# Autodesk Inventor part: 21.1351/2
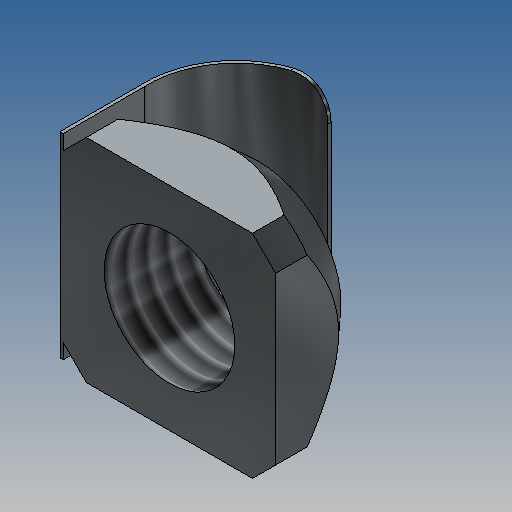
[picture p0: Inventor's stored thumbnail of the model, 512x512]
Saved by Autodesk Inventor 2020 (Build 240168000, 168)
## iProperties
Created: 2006-12
Part Number: 21.1351/2
Document SubType Name: Modeling
Designer: Andy Moles
Material: Steel, Mild
Density: 7.85 g/cm^3
Mass: 4.24899 g
Surface Area: 8.34272 cm^2
Volume: 0.541273 cm^3
Description: M8 SQUARE NUT POS FXG
Vendor: S
Appearance: Zinc
Title: M8 SQUARE NUT POS FXG
Author: Andy Moles
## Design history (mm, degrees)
sketch "Sketch2"
  geometry: L1 (-5.086, -6.5)-(5.086, -6.5); L2 (6.5, -5.086)-(6.5, 5.086); L3 (5.086, 6.5)-(-5.086, 6.5); L4 (-6.5, 5.086)-(-6.5, -5.086); L5 (-6.5, 6.5)-(6.5, -6.5); L6 (5.086, 6.5)-(6.5, 5.086); L7 (0, -6.5)-(0, 6.5); L8 (-6.5, 0)-(6.5, 0); L9 (-5.086, 6.5)-(-6.5, 5.086); L10 (-5.086, -6.5)-(-6.5, -5.086); L11 (5.086, -6.5)-(6.5, -5.086); C1 r 4 at (0, 0); 2 further points
  constraints: 22 end point, 6 symmetric about line, 4 parallel, 3 midpoint, 2 coincident, 2 perpendicular, 1 centre point, 1 horizontal
  dimensions: "THREAD" = 8 diameter of C1; "d3" = 45 deg angle of L3 L6 (derived); "d4" = 2 distance of L3.start L2.end
extrude "Extrusion1" new body sketch "Sketch2" distance "d5" = 5.5; taper "d6" = 0 deg
workplane "Work Plane1"
sketch "Sketch4"
  geometry: L1 (12.192, 0)-(4.192, 0) reference; L2 (8.192, 0)-(13.192, 0); L3 (16.385, 5.5)-(16.385, 3.5); L4 (13.192, 0)-(16.797, 3.952); L5 (13.192, 0)-(16.385, 0); L6 (16.385, 3.5)-(16.385, 0); L7 (16.797, 3.952)-(16.797, -0.412); L8 (16.797, -0.412)-(13.192, -0.412); L9 (13.192, -0.412)-(13.192, 0); L10 (8.192, 5.5)-(8.192, 0); L11 (16.385, 5.5)-(16.385, 0) reference; L12 (16.385, 3.5)-(17.502, 3.5); L13 (9.192, 5.5)-(16.385, 5.5) reference
  constraints: 20 end point, 6 perpendicular, 1 collinear, 1 midpoint, 1 parallel, 1 point on line
  dimensions: "d10" = 5 distance of L2.start L2.end; "d15" = 2 distance between parallel lines of L12 L13
revolve "Revolution1" sketch "Sketch4" stored, may be unused: angle "d12" = 90 deg
thread "Thread1" dims "d13" = 10, "d14" = 0
sketch "Sketch6"
  geometry: L1 (2.954, -2.535)-(2.954, 6.006); L2 (2.954, -2.535)-(2.954, -7.535); L3 (2.954, -2.535)-(3.154, -2.535); L4 (3.154, -2.535)-(3.154, -7.535); L5 (-2.646, -13.135)-(-2.646, -13.335); L6 (2.954, 0)-(2.954, -1.933); L7 (-8.632, -2.535)-(1.539, -2.535) reference; L8 (2.954, -2.535)-(2.954, -4.468) reference; A1 r 5.374 centre (-2.416, -7.766) between (-2.646, -13.135) and (2.954, -7.535); A2 r 5.574 centre (-2.416, -7.766) between (-2.646, -13.335) and (3.154, -7.535); 4 further points; 1 other entity
  constraints: 12 end point, 4 point on circle, 3 collinear, 2 centre point, 2 horizontal, 2 parallel, 2 perpendicular, 1 coincident, 3 other
  dimensions: "d25" = 5 distance of L1.start L2.end; "d23" = 0.2 distance of L1.start L3.end; "d22" = 0.2 distance of L5.start L5.end; "d21" = 10.8 distance from line of L5.end L3; "d24" = 5.37434 radius of A1
extrude "Extrusion3" join sketch "Sketch6" taper "d27" = 0 deg; stored distance "d28" = 12
fillet "Fillet2" dims "d29" = 2
body "Solid1"
